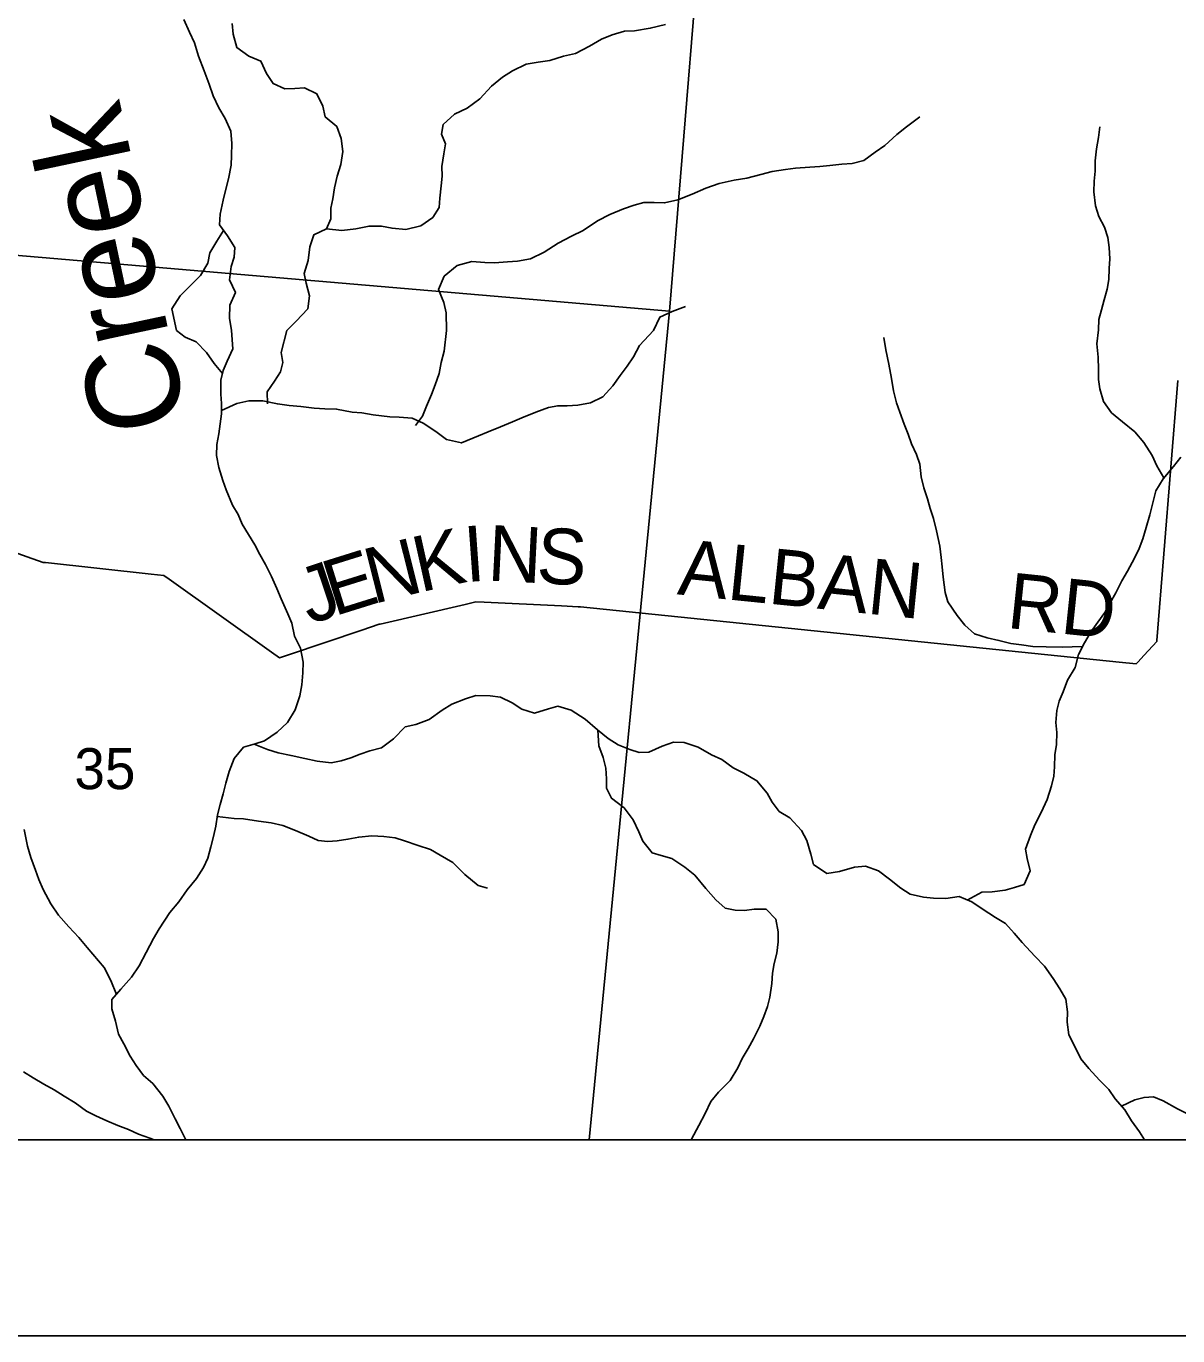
# Model space of a CAD drawing. Extents: x 0 to 42, y 0 to 22.
# Drawn here: x 7.225 to 7.812, y 14 to 14.668 of the extents above; entities that cross this region are included whole.
import ezdxf

# ---------------------------------------------------------------- set-up
doc = ezdxf.new("R2010")
doc.units = 0
for name, color, linetype in [('GM_X_Major_River', 7, 'Continuous'), ('GM_X_Major_River_Text', 7, 'Continuous'), ('GM_X_Minor_River', 7, 'Continuous'), ('GM_X_Section', 7, 'Continuous'), ('GM_X_Section_Text', 7, 'Continuous'), ('GM_X_Township_Road', 7, 'Continuous'), ('GM_X_Township_Road_Text', 7, 'Continuous'), ('GM_X_Unincorporated', 7, 'Continuous'), ('SH_Cut_Line', 7, 'Continuous'), ('SH_Data', 7, 'Continuous')]:
    doc.layers.add(name, color=color, linetype=linetype)

msp = doc.modelspace()

# ---------------------------------------------------------------- linework, layer by layer
at = {"layer": 'GM_X_Major_River'}
for points in [[(7.32927, 14.51288), (7.32831, 14.5192), (7.32849, 14.52584), (7.33131, 14.5323), (7.32828, 14.53874), (7.32921, 14.54557), (7.33071, 14.55032), (7.33108, 14.55525), (7.32729, 14.56131), (7.32312, 14.5668), (7.32348, 14.5723), (7.32498, 14.57951), (7.32649, 14.58502), (7.3278, 14.59033), (7.32911, 14.59735), (7.32929, 14.60228), (7.32947, 14.60835), (7.32889, 14.61461), (7.32604, 14.62105), (7.32282, 14.62655), (7.31997, 14.63261), (7.31788, 14.63868), (7.3154, 14.6455), (7.31255, 14.65289), (7.31046, 14.65972), (7.3078, 14.66521), (7.30495, 14.67166)], [(7.30053, 14.11066), (7.29731, 14.11711), (7.29428, 14.12223), (7.28916, 14.12868), (7.28442, 14.13285), (7.28063, 14.13797), (7.2776, 14.14271), (7.27437, 14.14897), (7.27172, 14.1539), (7.27021, 14.16054), (7.26831, 14.1668), (7.26831, 14.17154), (7.27286, 14.17685), (7.27836, 14.18293), (7.28216, 14.18881), (7.28576, 14.19564), (7.28956, 14.20266), (7.2924, 14.20759), (7.2979, 14.21594), (7.30245, 14.22145), (7.30663, 14.22752), (7.31137, 14.2334), (7.31497, 14.2389), (7.31725, 14.24365), (7.31877, 14.24953), (7.3201, 14.25484), (7.32124, 14.25996), (7.32219, 14.26584), (7.32351, 14.27116), (7.32503, 14.27647), (7.32636, 14.28197), (7.32807, 14.28785), (7.33072, 14.29449), (7.33547, 14.30038), (7.34134, 14.30209), (7.34609, 14.30361), (7.35253, 14.30797), (7.35784, 14.31291), (7.36183, 14.31936), (7.3641, 14.32657), (7.36524, 14.33207), (7.36562, 14.33833), (7.36582, 14.34364), (7.36449, 14.35085), (7.36146, 14.35692), (7.36013, 14.36356), (7.35805, 14.3683), (7.35464, 14.37608), (7.35236, 14.38139), (7.34971, 14.38746), (7.34668, 14.39353), (7.34383, 14.39865), (7.34118, 14.40358), (7.33474, 14.4142), (7.33265, 14.41913), (7.32981, 14.42387), (7.32659, 14.43165), (7.32488, 14.43639), (7.3228, 14.44303), (7.32166, 14.4491), (7.32185, 14.45479), (7.3228, 14.46029), (7.32356, 14.46541), (7.32413, 14.47035), (7.32413, 14.47566), (7.32394, 14.4804), (7.32395, 14.48761), (7.32509, 14.49254), (7.32717, 14.49729), (7.33002, 14.50355), (7.32927, 14.51288)], [(7.30605, 14.1), (7.30603, 14.10004), (7.30318, 14.10573), (7.30053, 14.11066)]]:
    msp.add_lwpolyline(points, dxfattribs=at)
at = {"layer": 'GM_X_Minor_River'}
for points in [[(7.35745, 14.5129), (7.36236, 14.51776), (7.36821, 14.52403), (7.36914, 14.53067), (7.36743, 14.53711), (7.36629, 14.54204), (7.36835, 14.54868), (7.36929, 14.5557), (7.37135, 14.56178), (7.37778, 14.56483), (7.38004, 14.56995), (7.38003, 14.57545), (7.38097, 14.58019), (7.3819, 14.5857), (7.38321, 14.59177), (7.38509, 14.59765), (7.38603, 14.60429), (7.38526, 14.61093), (7.38298, 14.617), (7.3771, 14.62192), (7.37596, 14.62741), (7.37292, 14.63367), (7.36649, 14.63669), (7.36157, 14.63649), (7.35646, 14.63629), (7.35059, 14.63893), (7.34718, 14.64405), (7.34433, 14.6503), (7.33809, 14.65294), (7.33202, 14.6573), (7.33012, 14.66412), (7.32973, 14.66962)], [(7.37774, 14.56481), (7.38554, 14.56389), (7.39272, 14.56485), (7.39953, 14.5662), (7.40577, 14.56621), (7.41126, 14.56508), (7.41825, 14.56453), (7.42582, 14.56644), (7.43205, 14.57062), (7.43525, 14.57575), (7.43562, 14.58049), (7.43618, 14.58676), (7.43674, 14.59169), (7.43654, 14.59662), (7.43766, 14.60307), (7.43841, 14.60819), (7.43651, 14.61312), (7.43726, 14.61805), (7.44311, 14.62338), (7.44953, 14.62642), (7.45595, 14.63118), (7.46199, 14.63764), (7.46747, 14.6422), (7.47257, 14.64544), (7.47956, 14.64887), (7.4858, 14.64983), (7.49166, 14.65079), (7.49866, 14.65289), (7.50471, 14.65423), (7.51189, 14.65803), (7.51812, 14.66165), (7.52341, 14.66375), (7.52984, 14.66566), (7.53495, 14.66586), (7.54289, 14.6672), (7.55064, 14.66911)], [(7.43896, 14.51295), (7.43876, 14.52189), (7.43762, 14.5272), (7.43496, 14.53383), (7.43778, 14.54067), (7.44439, 14.54618), (7.45195, 14.54809), (7.45857, 14.54773), (7.46349, 14.54755), (7.47011, 14.54794), (7.47521, 14.54833), (7.48183, 14.54948), (7.48882, 14.55291), (7.496, 14.55748), (7.5028, 14.56109), (7.50866, 14.56395), (7.51603, 14.5689), (7.52226, 14.57213), (7.52925, 14.57499), (7.53473, 14.5769), (7.53965, 14.57824), (7.54494, 14.57825), (7.55024, 14.57807), (7.55705, 14.5796), (7.56423, 14.58246), (7.57122, 14.58551), (7.57802, 14.58799), (7.58578, 14.58971), (7.5922, 14.59067), (7.59939, 14.59258), (7.60506, 14.59411), (7.61187, 14.59507), (7.61697, 14.59584), (7.62435, 14.59624), (7.62945, 14.59663), (7.63456, 14.59721), (7.64061, 14.59779), (7.6459, 14.59818), (7.65195, 14.59971), (7.65762, 14.60389), (7.66253, 14.60731), (7.66876, 14.61302), (7.67367, 14.61682), (7.68047, 14.62195)], [(7.77151, 14.51324), (7.7717, 14.51855), (7.77303, 14.52349), (7.77455, 14.52861), (7.77607, 14.53411), (7.77682, 14.53904), (7.77702, 14.54455), (7.7774, 14.54948), (7.77702, 14.55536), (7.77626, 14.56048), (7.77456, 14.5656), (7.77171, 14.5711), (7.77001, 14.5766), (7.76925, 14.58362), (7.76944, 14.58912), (7.76982, 14.59424), (7.76982, 14.59956), (7.77059, 14.60563), (7.77153, 14.61151), (7.77229, 14.61682)], [(7.32527, 14.56397), (7.32181, 14.55845), (7.31823, 14.55257), (7.31729, 14.54725), (7.31352, 14.54099), (7.3088, 14.53624), (7.30314, 14.53072), (7.2988, 14.52408), (7.30119, 14.51287)], [(7.5445, 14.51302), (7.54789, 14.51983), (7.55413, 14.52269), (7.56093, 14.52517)], [(7.32474, 14.49103), (7.32054, 14.49614), (7.31656, 14.50164), (7.31125, 14.50714), (7.30566, 14.50949), (7.30119, 14.51287)], [(7.32413, 14.47205), (7.3321, 14.47566), (7.33816, 14.47699), (7.34537, 14.47699), (7.35276, 14.47548), (7.35864, 14.47472), (7.36471, 14.47416), (7.37153, 14.4734), (7.37684, 14.47302), (7.38291, 14.47283), (7.39087, 14.47132), (7.3958, 14.47094), (7.40149, 14.47), (7.41002, 14.46886), (7.41477, 14.46867), (7.4214, 14.4683), (7.42709, 14.46564), (7.43353, 14.46147), (7.43903, 14.4573), (7.44662, 14.4556), (7.45534, 14.45921), (7.46027, 14.46129), (7.46653, 14.46376), (7.4726, 14.46642), (7.47734, 14.46832), (7.48454, 14.47136), (7.49099, 14.47364), (7.49573, 14.47459), (7.50047, 14.47459), (7.50597, 14.47478), (7.51242, 14.47611), (7.51867, 14.47915), (7.52379, 14.48465), (7.52759, 14.48997), (7.53119, 14.49471), (7.53442, 14.49945), (7.53745, 14.50534), (7.5445, 14.51302)], [(7.34764, 14.47548), (7.34746, 14.48174), (7.35125, 14.48705), (7.35428, 14.49179), (7.35542, 14.49654), (7.35467, 14.50166), (7.35745, 14.5129)], [(7.42311, 14.4645), (7.42671, 14.46925), (7.4288, 14.47437), (7.43126, 14.48025), (7.43316, 14.48519), (7.43525, 14.49107), (7.4362, 14.49657), (7.43772, 14.50245), (7.43896, 14.51295)], [(7.76343, 14.35177), (7.75812, 14.35158), (7.753, 14.35138), (7.74485, 14.35157), (7.73802, 14.35176), (7.73233, 14.35251), (7.72683, 14.35327), (7.72077, 14.35479), (7.7147, 14.35611), (7.70825, 14.35819), (7.70332, 14.36256), (7.69953, 14.36749), (7.69479, 14.3745), (7.69328, 14.37925), (7.69233, 14.38702), (7.69177, 14.39233), (7.69139, 14.39708), (7.69063, 14.40296), (7.68893, 14.41073), (7.68741, 14.41699), (7.68571, 14.42212), (7.68438, 14.42705), (7.68248, 14.43274), (7.68116, 14.43824), (7.6804, 14.44469), (7.6787, 14.44962), (7.67623, 14.45512), (7.67453, 14.46005), (7.67244, 14.46517), (7.67017, 14.47124), (7.66846, 14.47598), (7.66695, 14.48224), (7.666, 14.4885), (7.66468, 14.49571), (7.66316, 14.50311), (7.66203, 14.50937)], [(7.80493, 14.43774), (7.80137, 14.44398), (7.79891, 14.4491), (7.79474, 14.45574), (7.79019, 14.46124), (7.78374, 14.46636), (7.77825, 14.47091), (7.77408, 14.47679), (7.77218, 14.48323), (7.77161, 14.48798), (7.77162, 14.4931), (7.77143, 14.49936), (7.77067, 14.50619), (7.77151, 14.51324)], [(7.70462, 14.22235), (7.71201, 14.22635), (7.71732, 14.22655), (7.72396, 14.22731), (7.7287, 14.22883), (7.73363, 14.23035), (7.73666, 14.23718), (7.73515, 14.24362), (7.73439, 14.24837), (7.73686, 14.2552), (7.73913, 14.2607), (7.74236, 14.26696), (7.74539, 14.2736), (7.74767, 14.28062), (7.74881, 14.28555), (7.74919, 14.2903), (7.74938, 14.29637), (7.75014, 14.30168), (7.75033, 14.30775), (7.74977, 14.31287), (7.75034, 14.31913), (7.75147, 14.32388), (7.75356, 14.32862), (7.75584, 14.3345), (7.75963, 14.34095), (7.76134, 14.34759), (7.76438, 14.35366), (7.76779, 14.35936), (7.7712, 14.3641), (7.77481, 14.36903), (7.77746, 14.37397), (7.7805, 14.37909), (7.78353, 14.38516), (7.78638, 14.3901), (7.78998, 14.39674), (7.79226, 14.40167), (7.79416, 14.4066), (7.79586, 14.41249), (7.79776, 14.41894), (7.8008, 14.43108), (7.80459, 14.43734), (7.8099, 14.4436), (7.81351, 14.44835)], [(7.34081, 14.30193), (7.3476, 14.29924), (7.3531, 14.29754), (7.35974, 14.29602), (7.36675, 14.29451), (7.37301, 14.29318), (7.38021, 14.29243), (7.38533, 14.29338), (7.39026, 14.2949), (7.395, 14.2968), (7.39993, 14.2985), (7.40581, 14.30002), (7.41188, 14.30458), (7.41795, 14.31065), (7.42326, 14.31198), (7.43009, 14.31445), (7.43672, 14.3192), (7.44165, 14.32223), (7.44867, 14.32508), (7.45398, 14.32679), (7.46118, 14.32661), (7.46649, 14.32585), (7.47256, 14.32301), (7.47749, 14.31978), (7.48394, 14.3177), (7.49095, 14.31998), (7.49569, 14.32131), (7.50252, 14.31922), (7.50972, 14.31467), (7.51598, 14.30917), (7.52147, 14.30481), (7.52659, 14.30159), (7.53247, 14.29913), (7.53721, 14.29761), (7.54214, 14.2978), (7.54897, 14.30084), (7.55485, 14.30293), (7.56015, 14.30274), (7.56736, 14.30028), (7.57418, 14.29649), (7.57949, 14.29402), (7.58518, 14.28985), (7.59068, 14.28701), (7.59731, 14.28322), (7.60262, 14.27696), (7.60508, 14.27222), (7.60869, 14.26748), (7.61418, 14.26425), (7.62006, 14.25781), (7.62271, 14.25269), (7.6248, 14.24567), (7.62612, 14.24055), (7.63295, 14.23581), (7.63939, 14.23695), (7.64717, 14.23904), (7.65267, 14.23961), (7.6593, 14.23733), (7.66499, 14.23297), (7.67068, 14.22842), (7.67542, 14.22539), (7.68224, 14.22387), (7.68736, 14.22331), (7.69362, 14.22312), (7.70045, 14.22407), (7.70689, 14.22142), (7.7122, 14.21782), (7.71902, 14.21346), (7.72414, 14.21042), (7.7285, 14.20549), (7.73267, 14.20075), (7.73912, 14.19373), (7.74405, 14.18862), (7.74841, 14.18236), (7.75182, 14.17705), (7.75485, 14.17173), (7.7558, 14.16529), (7.7556, 14.15997), (7.75636, 14.15353), (7.75977, 14.14689), (7.76262, 14.14139), (7.7666, 14.13646), (7.77209, 14.13039), (7.77683, 14.12565), (7.78005, 14.12091), (7.78498, 14.11522), (7.78839, 14.10972), (7.79256, 14.10403), (7.79498, 14.1)], [(7.51613, 14.30905), (7.51673, 14.30102), (7.51882, 14.29514), (7.52033, 14.28964), (7.52052, 14.28414), (7.52052, 14.27939), (7.52317, 14.27427), (7.52962, 14.26934), (7.53417, 14.26327), (7.53701, 14.2572), (7.53909, 14.25246), (7.54383, 14.24639), (7.54857, 14.24507), (7.55388, 14.24355), (7.56052, 14.23919), (7.56564, 14.23502), (7.57132, 14.22819), (7.57644, 14.2225), (7.58118, 14.21814), (7.5863, 14.2172), (7.59104, 14.21701), (7.59597, 14.21777), (7.60204, 14.21777), (7.60696, 14.21265), (7.6081, 14.2062), (7.6081, 14.20108), (7.60753, 14.1952), (7.6062, 14.18989), (7.60525, 14.18495), (7.60487, 14.17983), (7.60392, 14.17281), (7.60278, 14.16807), (7.60089, 14.16295), (7.5988, 14.15801), (7.59557, 14.15156), (7.59292, 14.14663), (7.58988, 14.14151), (7.58761, 14.13676), (7.58362, 14.13031), (7.57774, 14.12424), (7.57376, 14.11949), (7.57091, 14.11342), (7.56769, 14.10735), (7.56389, 14.10033), (7.56373, 14.1)], [(7.32204, 14.26494), (7.33072, 14.26395), (7.33546, 14.26376), (7.34304, 14.26263), (7.34949, 14.26168), (7.35555, 14.26036), (7.362, 14.25789), (7.36883, 14.25486), (7.37357, 14.25278), (7.3785, 14.25221), (7.38324, 14.25259), (7.38873, 14.25335), (7.39423, 14.25449), (7.40087, 14.25506), (7.40694, 14.25469), (7.41282, 14.25412), (7.41755, 14.2526), (7.42457, 14.25014), (7.43083, 14.24806), (7.43576, 14.24521), (7.4422, 14.24142), (7.44827, 14.23535), (7.45509, 14.22985), (7.45983, 14.22834)], [(7.27058, 14.17418), (7.26775, 14.18122), (7.26433, 14.18785), (7.25561, 14.19809), (7.25144, 14.20321), (7.24633, 14.20871), (7.24102, 14.21459), (7.23723, 14.22047), (7.23325, 14.22768), (7.23097, 14.2328), (7.22927, 14.23754), (7.227, 14.24399), (7.22529, 14.24987), (7.22359, 14.25841)], [(7.28983, 14.1), (7.28764, 14.10079), (7.28195, 14.10287), (7.27683, 14.10534), (7.27133, 14.10723), (7.26564, 14.1097), (7.26014, 14.11216), (7.25541, 14.11462), (7.24953, 14.1188), (7.24403, 14.12221), (7.23891, 14.12543), (7.2336, 14.12846), (7.22811, 14.13169), (7.22318, 14.13472)], [(7.78334, 14.11711), (7.7901, 14.12034), (7.79484, 14.12167), (7.79958, 14.12186), (7.80451, 14.11997), (7.81191, 14.1158), (7.81835, 14.11257), (7.82347, 14.11087), (7.82992, 14.10822), (7.83542, 14.10556), (7.84053, 14.10101), (7.84155, 14.1)]]:
    msp.add_lwpolyline(points, dxfattribs=at)
at = {"layer": 'GM_X_Section'}
msp.add_lwpolyline([(7.06657, 15.07902), (7.59454, 15.03393), (7.55266, 14.52283), (7.02582, 14.56792)], close=True, dxfattribs=at)
at = {"layer": 'GM_X_Township_Road'}
for points in [[(4.80642, 14.1), (8.05023, 14.1), (8.06868, 14.30702), (8.08338, 14.51358), (8.1512, 15.24132), (8.15761, 15.31908), (8.1628, 15.37905), (8.16837, 15.44612), (8.16945, 15.45935), (8.16983, 15.46634), (8.17227, 15.49063), (8.24231, 16.32059)], [(7.81208, 14.4875), (7.80134, 14.35479), (7.80129, 14.3543), (7.79494, 14.34737), (7.79162, 14.34373), (7.79086, 14.3429), (7.78216, 14.34378), (7.50741, 14.3719), (7.5062, 14.372), (7.49757, 14.37241), (7.45816, 14.37428), (7.45401, 14.37448), (7.44844, 14.37319), (7.4052, 14.36319), (7.40467, 14.36307), (7.39584, 14.3601), (7.35844, 14.34752), (7.35381, 14.34596), (7.34975, 14.34885), (7.29753, 14.38604), (7.29479, 14.38799), (7.28832, 14.38868), (7.23439, 14.39453), (7.23331, 14.39464), (7.22502, 14.39755), (7.21106, 14.40245)]]:
    msp.add_lwpolyline(points, dxfattribs=at)
at = {"layer": 'GM_X_Unincorporated'}
msp.add_lwpolyline([(6.98185, 14.1), (7.51177, 14.1), (7.55266, 14.52283), (7.02582, 14.56792)], close=True, dxfattribs=at)
at = {"layer": 'SH_Cut_Line'}
msp.add_lwpolyline([(2.1, 20.9), (2.1, 14.1), (8.05023, 14.1), (8.06868, 14.30702), (8.08338, 14.51358), (8.1512, 15.24132), (8.15761, 15.31908), (8.1628, 15.37905), (8.16837, 15.44612), (8.16945, 15.45935), (8.16983, 15.46634), (8.17227, 15.49063), (8.24231, 16.32059)], dxfattribs=at)
at = {"layer": 'SH_Data'}
for p, q in [((2.1, 14.1), (8.9, 14.1)), ((2, 14), (9, 14))]:
    msp.add_line(p, q, dxfattribs=at)

# ---------------------------------------------------------------- texts
at = {"layer": 'GM_X_Major_River_Text'}
msp.add_text('Creek', height=0.047353, rotation=101.99899, dxfattribs=at).set_placement((7.3071, 14.46608))
at = {"layer": 'GM_X_Section_Text'}
msp.add_text('35', height=0.020928, rotation=0.00001, dxfattribs=at).set_placement((7.24917, 14.27893))
at = {"layer": 'GM_X_Township_Road_Text'}
for s, height, rotation, p in [('N', 0.02841, 357.11377, (7.45956, 14.38539)), ('K', 0.02841, 12.58452, (7.42554, 14.37929)), ('I', 0.02841, 4.09396, (7.44884, 14.38457)), ('S', 0.02841, 356.92428, (7.48451, 14.38414)), ('E', 0.02841, 17.34124, (7.38161, 14.36703)), ('N', 0.02841, 14.08218, (7.40149, 14.37325)), ('ALBAN', 0.028409, 354.19347, (7.55635, 14.37836)), ('J', 0.02841, 18.6099, (7.36913, 14.36283)), ('RD', 0.028409, 354.04244, (7.72429, 14.36126))]:
    msp.add_text(s, height=height, rotation=rotation, dxfattribs=at).set_placement(p)

doc.saveas('drawing.dxf')
